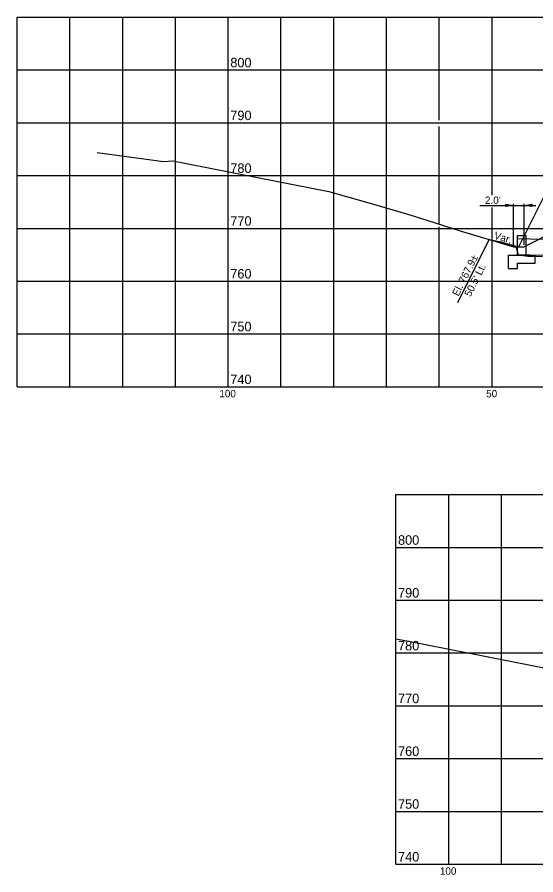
# Model space of a CAD drawing. Extents: x -1395 to 1843, y -1176 to 1887.
# Drawn here: x -622.7 to -426.1, y -773.2 to -448.3 of the extents above; entities that cross this region are included whole.
import ezdxf

# ---------------------------------------------------------------- set-up
doc = ezdxf.new("R2010")
doc.units = 0
for name, color, linetype in [('DR_X_Storm_Sewer', 7, 'Continuous'), ('GE_X_Alignment', 7, 'Continuous'), ('HY_X_Water_Edge', 7, 'Continuous'), ('MT_P_Temp_Road', 7, 'Continuous'), ('RW_P_Esmt_SH', 7, 'Continuous'), ('RW_P_Esmt_TMP', 7, 'Continuous'), ('SH_Data', 7, 'Continuous'), ('SV_X_Break_Lines', 7, 'Continuous'), ('SV_X_Random_Point', 7, 'Continuous')]:
    doc.layers.add(name, color=color, linetype=linetype)

msp = doc.modelspace()

# ---------------------------------------------------------------- linework, layer by layer
at = {"layer": 'DR_X_Storm_Sewer'}
for p, q in [((-380.71, -510.32), (-430.6, -535.27)), ((-443.8, -532.45), (-434.6, -535.27)), ((-434.6, -535.27), (-430.6, -535.27))]:
    msp.add_line(p, q, dxfattribs=at)
at = {"layer": 'GE_X_Alignment'}
for p, q in [((-622.71, -448.27), (-62.71, -448.27)), ((-432.6, -535.27), (-414.68, -499.44)), ((-447.29, -519.56), (-434.6, -519.56)), ((-434.6, -519.56), (-430.6, -519.56)), ((-430.6, -519.56), (-426.12, -519.56)), ((-455.73, -556.31), (-443.8, -532.45)), ((-479.14, -629.14), (-39.14, -629.14))]:
    msp.add_line(p, q, dxfattribs=at)
at = {"layer": 'HY_X_Water_Edge'}
for p, q in [((-592.35, -499.59), (-567.27, -502.99)), ((-567.27, -502.99), (-563.64, -502.74)), ((-563.64, -502.74), (-558.55, -503.67)), ((-558.55, -503.67), (-531.59, -508.99)), ((-531.59, -508.99), (-504.62, -514.31)), ((-504.62, -514.31), (-489.42, -518.66)), ((-489.42, -518.66), (-474.22, -523.01)), ((-474.22, -523.01), (-464.29, -526.15)), ((-464.29, -526.15), (-454.36, -529.29)), ((-454.36, -529.29), (-443.8, -532.45)), ((-443.8, -532.45), (-439.97, -533.28)), ((-439.97, -533.28), (-436.85, -534.18)), ((-436.85, -534.18), (-433.73, -535.08)), ((-433.73, -535.08), (-432.8, -538.35)), ((-432.8, -538.35), (-429.14, -538.83)), ((-429.14, -538.83), (-423.57, -538.88))]:
    msp.add_line(p, q, dxfattribs=at)
msp.add_lwpolyline([(-479.14, -683.78), (-474.98, -684.55), (-421.05, -695.19)], dxfattribs=at)
at = {"layer": 'MT_P_Temp_Road'}
for p, q in [((-342.71, -534.79), (-433.1, -532.27)), ((-433.1, -538.27), (-433.1, -532.27)), ((-342.71, -540.79), (-433.1, -538.27))]:
    msp.add_line(p, q, dxfattribs=at)
at = {"layer": 'RW_P_Esmt_SH'}
for p, q in [((-433.1, -530.93), (-429.74, -530.93)), ((-433.1, -532.27), (-433.1, -530.93)), ((-429.74, -532.35), (-429.74, -530.93)), ((-429.74, -538.34), (-429.74, -532.35)), ((-436.45, -543.43), (-436.45, -538.43)), ((-436.45, -538.43), (-426.39, -538.43)), ((-426.39, -541.43), (-426.39, -538.43)), ((-433.1, -541.43), (-426.39, -541.43)), ((-433.1, -543.43), (-433.1, -541.43)), ((-436.45, -543.43), (-433.1, -543.43))]:
    msp.add_line(p, q, dxfattribs=at)
at = {"layer": 'RW_P_Esmt_TMP'}
for p, q in [((-622.71, -588.27), (-622.71, -448.27)), ((-602.71, -588.27), (-602.71, -448.27)), ((-582.71, -588.27), (-582.71, -448.27)), ((-562.71, -588.27), (-562.71, -448.27)), ((-542.71, -588.27), (-542.71, -448.27)), ((-522.71, -588.27), (-522.71, -448.27)), ((-502.71, -588.27), (-502.71, -448.27)), ((-482.71, -588.27), (-482.71, -448.27)), ((-462.71, -487.33), (-462.71, -448.27)), ((-442.71, -515.73), (-442.71, -448.27)), ((-622.71, -468.27), (-62.71, -468.27)), ((-622.71, -488.27), (-62.71, -488.27)), ((-622.71, -508.27), (-62.71, -508.27)), ((-442.71, -588.27), (-442.71, -520.38)), ((-622.71, -528.27), (-62.71, -528.27)), ((-462.71, -588.27), (-462.71, -527.66)), ((-622.71, -548.27), (-62.71, -548.27)), ((-622.71, -568.27), (-62.71, -568.27)), ((-622.71, -588.27), (-62.71, -588.27)), ((-479.14, -769.14), (-479.14, -629.14)), ((-459.14, -769.14), (-459.14, -629.14)), ((-439.14, -769.14), (-439.14, -629.14)), ((-479.14, -649.14), (-39.14, -649.14)), ((-479.14, -669.14), (-39.14, -669.14)), ((-479.14, -689.14), (-39.14, -689.14)), ((-479.14, -709.14), (-39.14, -709.14)), ((-479.14, -729.14), (-39.14, -729.14)), ((-479.14, -749.14), (-39.14, -749.14)), ((-479.14, -769.14), (-39.14, -769.14))]:
    msp.add_line(p, q, dxfattribs=at)
at = {"layer": 'SV_X_Break_Lines'}
msp.add_line((-462.71, -526.65), (-462.71, -489.74), dxfattribs=at)
at = {"layer": 'SV_X_Random_Point'}
for p, q in [((-434.6, -519.56), (-437.56, -520.05)), ((-437.55, -519.06), (-437.55, -519.06)), ((-437.55, -519.06), (-434.6, -519.56)), ((-434.6, -534.54), (-434.6, -518.96)), ((-430.6, -534.54), (-430.6, -518.96)), ((-430.6, -519.56), (-427.63, -519.06)), ((-427.64, -520.05), (-430.6, -519.56)), ((-427.63, -519.06), (-427.63, -519.06)), ((-437.56, -520.05), (-437.56, -520.05)), ((-427.64, -520.05), (-427.64, -520.05))]:
    msp.add_line(p, q, dxfattribs=at)
for centre, start, end in [((-438.31, -519.55), 326.178, 32.8588), ((-426.88, -519.56), 146.178, 212.8588)]:
    msp.add_arc(centre, 0.9, start, end, dxfattribs=at)

# ---------------------------------------------------------------- texts
at = {"layer": 'SH_Data'}
for s, height, p in [('800', 3.6, (-541.91, -467.27)), ('790', 3.6, (-541.91, -487.27)), ('780', 3.6, (-541.91, -507.27)), ("2.0'", 2.8, (-445.4, -519.01)), ('770', 3.6, (-541.91, -527.27)), ('760', 3.6, (-541.91, -547.27)), ('750', 3.6, (-541.91, -567.27)), ('740', 3.6, (-541.91, -587.27)), ('100', 2.8, (-546.06, -592.27)), ('50', 2.8, (-444.94, -592.27)), ('800', 3.6, (-478.34, -648.14)), ('790', 3.6, (-478.34, -668.14)), ('780', 3.6, (-478.34, -688.14)), ('770', 3.6, (-478.34, -708.14)), ('760', 3.6, (-478.34, -728.14)), ('750', 3.6, (-478.34, -748.14)), ('740', 3.6, (-478.34, -768.14)), ('100', 2.8, (-462.48, -773.14))]:
    msp.add_text(s, height=height, dxfattribs=at).set_placement(p)
for s, rotation, p in [('Var.', 342.9833, (-442.2, -532.14)), ('El. 767.9±', 63.4349, (-455.46, -554.21)), ("50.5' Lt.", 63.4349, (-450.86, -554.39))]:
    msp.add_text(s, height=2.8, rotation=rotation, dxfattribs=at).set_placement(p)

doc.saveas('drawing.dxf')
